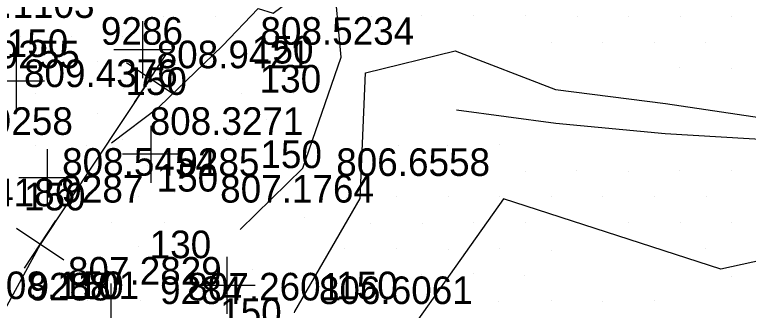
# Model space of a CAD drawing. Extents: x 1602514 to 1609837, y 863887 to 871157.
# Drawn here: x 1605194.3 to 1605395.4, y 866734.2 to 866815.2 of the extents above; entities that cross this region are included whole.
import ezdxf

# ---------------------------------------------------------------- set-up
doc = ezdxf.new("R2010")
doc.units = 0
for name, color, linetype in [('Default', 7, 'Continuous'), ('Survey-Entrances', 7, 'Continuous'), ('Survey-Point', 7, 'Continuous'), ('Survey-Ridge Lines', 7, 'Continuous'), ('Survey-Spot dirt', 7, 'Continuous'), ('Survey-Text-Elevation', 7, 'Continuous'), ('Survey-Text-Feature', 7, 'Continuous'), ('Survey-Text-Name and Number', 7, 'Continuous'), ('Survey-Vegetation trees', 7, 'Continuous')]:
    doc.layers.add(name, color=color, linetype=linetype)

msp = doc.modelspace()

# ---------------------------------------------------------------- linework, layer by layer
at = {"layer": 'Default'}
msp.add_lwpolyline([(1605231.48, 866797.64), (1605201.32, 866752.26), (1605178.92, 866711.24), (1605159.12, 866669.05), (1605154.12, 866645.56), (1605149.73, 866618.16), (1605145.78, 866600.99), (1605148.09, 866583.95), (1605152.17, 866572.39), (1605154.66, 866567.14)], dxfattribs=at)
msp.add_lwpolyline([(1605231.48, 866797.64), (1605201.32, 866752.26), (1605178.92, 866711.24), (1605159.12, 866669.05), (1605154.12, 866645.56), (1605149.73, 866618.16), (1605145.78, 866600.99), (1605148.09, 866583.95), (1605152.17, 866572.39), (1605154.66, 866567.14)], dxfattribs=at)
at = {"layer": 'Survey-Entrances'}
msp.add_lwpolyline([(1605220.9, 866780.04), (1605233.94, 866789.98), (1605251.28, 866806.63), (1605261.09, 866816.87), (1605265.22, 866815.59), (1605277.16, 866824.55), (1605284.83, 866835.5), (1605285.97, 866842.76), (1605266.64, 866853.28), (1605249.72, 866867.37), (1605246.59, 866870.64), (1605249.72, 866873.06), (1605223.7, 866894.39), (1605223.7, 866899.94), (1605224.56, 866909.9), (1605231.81, 866921.14), (1605236.92, 866929.25), (1605246.17, 866924.55), (1605248.44, 866924.98), (1605244.46, 866933.37), (1605248.44, 866951.15)], dxfattribs=at)
msp.add_lwpolyline([(1605220.9, 866780.04), (1605233.94, 866789.98), (1605251.28, 866806.63), (1605261.09, 866816.87), (1605265.22, 866815.59), (1605277.16, 866824.55), (1605284.83, 866835.5), (1605285.97, 866842.76), (1605266.64, 866853.28), (1605249.72, 866867.37), (1605246.59, 866870.64), (1605249.72, 866873.06), (1605223.7, 866894.39), (1605223.7, 866899.94), (1605224.56, 866909.9), (1605231.81, 866921.14), (1605236.92, 866929.25), (1605246.17, 866924.55), (1605248.44, 866924.98), (1605244.46, 866933.37), (1605248.44, 866951.15)], dxfattribs=at)
at = {"layer": 'Survey-Point'}
for p, q in [((1605227.15, 866791.13), (1605235.8, 866804.15)), ((1605237.98, 866793.32), (1605224.97, 866801.96)), ((1605197, 866745.75), (1605205.64, 866758.77)), ((1605207.83, 866747.93), (1605194.81, 866756.58))]:
    msp.add_line(p, q, dxfattribs=at)
at = {"layer": 'Survey-Ridge Lines'}
for points in [[(1605256.12, 866756.37), (1605273.32, 866773.13), (1605283.85, 866803.56), (1605281.75, 866826.44)], [(1605256.13, 866756.37), (1605273.32, 866773.13), (1605283.85, 866803.56), (1605281.75, 866826.44)], [(1605271.01, 866733.55), (1605271.13, 866733.84), (1605289.06, 866764.85), (1605290.46, 866799.29), (1605315.08, 866805.27), (1605342.58, 866794.72), (1605372.7, 866790.88), (1605403.41, 866786.28), (1605432.05, 866784.47), (1605463.64, 866786.21), (1605496.91, 866792.44), (1605533.57, 866796.29), (1605572.16, 866793.97)], [(1605271.13, 866733.84), (1605289.06, 866764.85), (1605290.46, 866799.29), (1605315.08, 866805.27), (1605342.58, 866794.72), (1605372.7, 866790.88), (1605403.41, 866786.28), (1605432.05, 866784.47), (1605463.64, 866786.21), (1605496.91, 866792.44), (1605533.57, 866796.29), (1605572.16, 866793.97)], [(1605315.46, 866789.1), (1605342.69, 866785.48), (1605372.69, 866782.64), (1605403.34, 866780.84), (1605431.74, 866777.29), (1605465.29, 866777.04), (1605496.99, 866781.93), (1605532.71, 866782.11), (1605571.74, 866783.81)], [(1605315.46, 866789.1), (1605342.69, 866785.48), (1605372.69, 866782.64), (1605403.34, 866780.84), (1605431.74, 866777.29), (1605465.29, 866777.04), (1605496.99, 866781.93), (1605532.71, 866782.11), (1605571.74, 866783.81)]]:
    msp.add_lwpolyline(points, dxfattribs=at)
at = {"layer": 'Survey-Spot dirt'}
for p, q in [((1605229.36, 866813.39), (1605229.36, 866797.77)), ((1605235.21, 866814.77), (1605235.21, 866814.77)), ((1605235.21, 866814.77), (1605235.21, 866814.77)), ((1605249.42, 866814.81), (1605249.42, 866814.81)), ((1605249.42, 866814.81), (1605249.42, 866814.81)), ((1605277.86, 866814.78), (1605277.86, 866814.78)), ((1605277.86, 866814.78), (1605277.86, 866814.78)), ((1605292.21, 866814.71), (1605292.21, 866814.71)), ((1605292.21, 866814.71), (1605292.21, 866814.71)), ((1605305.71, 866814.99), (1605305.71, 866814.99)), ((1605305.71, 866814.99), (1605305.71, 866814.99)), ((1605320.14, 866814.86), (1605320.14, 866814.86)), ((1605320.14, 866814.86), (1605320.14, 866814.86)), ((1605334.29, 866814.84), (1605334.29, 866814.84)), ((1605334.29, 866814.84), (1605334.29, 866814.84)), ((1605348.6, 866814.69), (1605348.6, 866814.69)), ((1605348.6, 866814.69), (1605348.6, 866814.69)), ((1605362.56, 866814.74), (1605362.56, 866814.74)), ((1605362.56, 866814.74), (1605362.56, 866814.74)), ((1605376.78, 866814.73), (1605376.78, 866814.73)), ((1605376.78, 866814.73), (1605376.78, 866814.73)), ((1605390.84, 866814.81), (1605390.84, 866814.81)), ((1605390.84, 866814.81), (1605390.84, 866814.81)), ((1605195.79, 866809.34), (1605195.79, 866809.34)), ((1605195.79, 866809.34), (1605195.79, 866809.34)), ((1605209.88, 866809.32), (1605209.88, 866809.32)), ((1605209.88, 866809.32), (1605209.88, 866809.32)), ((1605223.91, 866809.29), (1605223.91, 866809.29)), ((1605223.91, 866809.29), (1605223.91, 866809.29)), ((1605242.33, 866807.76), (1605242.33, 866807.76)), ((1605242.33, 866807.76), (1605242.33, 866807.76)), ((1605256.51, 866807.63), (1605256.51, 866807.63)), ((1605256.51, 866807.63), (1605256.51, 866807.63)), ((1605270.59, 866807.72), (1605270.59, 866807.72)), ((1605270.59, 866807.72), (1605270.59, 866807.72)), ((1605284.99, 866807.38), (1605284.99, 866807.38)), ((1605284.99, 866807.38), (1605284.99, 866807.38)), ((1605341.53, 866807.53), (1605341.53, 866807.53)), ((1605341.53, 866807.53), (1605341.53, 866807.53)), ((1605355.54, 866807.62), (1605355.54, 866807.62)), ((1605355.54, 866807.62), (1605355.54, 866807.62)), ((1605369.65, 866807.47), (1605369.65, 866807.47)), ((1605369.65, 866807.47), (1605369.65, 866807.47)), ((1605383.82, 866807.56), (1605383.82, 866807.56)), ((1605383.82, 866807.56), (1605383.82, 866807.56)), ((1605237.17, 866805.58), (1605221.54, 866805.58)), ((1605194.68, 866804.79), (1605194.68, 866789.16)), ((1605202.91, 866802.22), (1605202.91, 866802.22)), ((1605202.91, 866802.22), (1605202.91, 866802.22)), ((1605216.96, 866802.24), (1605216.96, 866802.24)), ((1605216.96, 866802.24), (1605216.96, 866802.24)), ((1605231.03, 866802.3), (1605231.03, 866802.3)), ((1605231.03, 866802.3), (1605231.03, 866802.3)), ((1605249.36, 866800.65), (1605249.36, 866800.65)), ((1605249.36, 866800.65), (1605249.36, 866800.65)), ((1605263.73, 866800.88), (1605263.73, 866800.88)), ((1605263.73, 866800.88), (1605263.73, 866800.88)), ((1605277.67, 866800.78), (1605277.67, 866800.78)), ((1605277.67, 866800.78), (1605277.67, 866800.78)), ((1605376.64, 866800.66), (1605376.64, 866800.66)), ((1605376.64, 866800.66), (1605376.64, 866800.66)), ((1605390.94, 866800.57), (1605390.94, 866800.57)), ((1605390.94, 866800.57), (1605390.94, 866800.57)), ((1605202.49, 866796.98), (1605186.87, 866796.98)), ((1605200.02, 866793.56), (1605200.02, 866793.56)), ((1605200.02, 866793.56), (1605200.02, 866793.56)), ((1605209.85, 866795.02), (1605209.85, 866795.02)), ((1605209.85, 866795.02), (1605209.85, 866795.02)), ((1605224.21, 866795.08), (1605224.21, 866795.08)), ((1605224.21, 866795.08), (1605224.21, 866795.08)), ((1605256.6, 866793.61), (1605256.6, 866793.61)), ((1605256.6, 866793.61), (1605256.6, 866793.61)), ((1605270.76, 866793.59), (1605270.76, 866793.59)), ((1605270.76, 866793.59), (1605270.76, 866793.59)), ((1605217.08, 866788.14), (1605217.08, 866788.14)), ((1605217.08, 866788.14), (1605217.08, 866788.14)), ((1605245.27, 866788.07), (1605245.27, 866788.07)), ((1605245.27, 866788.07), (1605245.27, 866788.07)), ((1605207.02, 866786.5), (1605207.02, 866786.5)), ((1605207.02, 866786.5), (1605207.02, 866786.5)), ((1605263.27, 866786.39), (1605263.27, 866786.39)), ((1605263.27, 866786.39), (1605263.27, 866786.39)), ((1605231.68, 866784.75), (1605231.68, 866769.13)), ((1605199.93, 866779.41), (1605199.93, 866779.41)), ((1605199.93, 866779.41), (1605199.93, 866779.41)), ((1605214.03, 866779.42), (1605214.03, 866779.42)), ((1605214.03, 866779.42), (1605214.03, 866779.42)), ((1605224, 866781.05), (1605224, 866781.05)), ((1605224, 866781.05), (1605224, 866781.05)), ((1605238.21, 866781.02), (1605238.21, 866781.02)), ((1605238.21, 866781.02), (1605238.21, 866781.02)), ((1605252.3, 866781.08), (1605252.3, 866781.08)), ((1605252.3, 866781.08), (1605252.3, 866781.08)), ((1605299.45, 866779.28), (1605299.45, 866779.28)), ((1605299.45, 866779.28), (1605299.45, 866779.28)), ((1605313.07, 866779.4), (1605313.07, 866779.4)), ((1605313.07, 866779.4), (1605313.07, 866779.4)), ((1605327.22, 866779.52), (1605327.22, 866779.52)), ((1605327.22, 866779.52), (1605327.22, 866779.52)), ((1605203.24, 866778.32), (1605203.24, 866762.7)), ((1605239.49, 866776.94), (1605223.86, 866776.94)), ((1605230.84, 866773.98), (1605230.84, 866773.98)), ((1605230.84, 866773.98), (1605230.84, 866773.98)), ((1605245.22, 866773.7), (1605245.22, 866773.7)), ((1605245.22, 866773.7), (1605245.22, 866773.7)), ((1605206.97, 866772.41), (1605206.97, 866772.41)), ((1605206.97, 866772.41), (1605206.97, 866772.41)), ((1605221.41, 866772.37), (1605221.41, 866772.37)), ((1605221.41, 866772.37), (1605221.41, 866772.37)), ((1605306.05, 866772.31), (1605306.05, 866772.31)), ((1605306.05, 866772.31), (1605306.05, 866772.31)), ((1605320.24, 866772.27), (1605320.24, 866772.27)), ((1605320.24, 866772.27), (1605320.24, 866772.27)), ((1605334.25, 866772.36), (1605334.25, 866772.36)), ((1605334.25, 866772.36), (1605334.25, 866772.36)), ((1605348.37, 866772.39), (1605348.37, 866772.39)), ((1605348.37, 866772.39), (1605348.37, 866772.39)), ((1605362.68, 866772.27), (1605362.68, 866772.27)), ((1605362.68, 866772.27), (1605362.68, 866772.27)), ((1605376.7, 866772.39), (1605376.7, 866772.39)), ((1605376.7, 866772.39), (1605376.7, 866772.39)), ((1605390.79, 866772.41), (1605390.79, 866772.41)), ((1605390.79, 866772.41), (1605390.79, 866772.41)), ((1605211.05, 866770.51), (1605195.43, 866770.51)), ((1605199.94, 866765.36), (1605199.94, 866765.36)), ((1605199.94, 866765.36), (1605199.94, 866765.36)), ((1605214.08, 866765.3), (1605214.08, 866765.3)), ((1605214.08, 866765.3), (1605214.08, 866765.3)), ((1605228.19, 866765.42), (1605228.19, 866765.42)), ((1605228.19, 866765.42), (1605228.19, 866765.42)), ((1605238.14, 866766.51), (1605238.14, 866766.51)), ((1605238.14, 866766.51), (1605238.14, 866766.51)), ((1605252.66, 866766.97), (1605252.66, 866766.97)), ((1605252.66, 866766.97), (1605252.66, 866766.97)), ((1605285.15, 866765.1), (1605285.15, 866765.1)), ((1605285.15, 866765.1), (1605285.15, 866765.1)), ((1605298.96, 866765.28), (1605298.96, 866765.28)), ((1605298.96, 866765.28), (1605298.96, 866765.28)), ((1605313.13, 866765.28), (1605313.13, 866765.28)), ((1605313.13, 866765.28), (1605313.13, 866765.28)), ((1605327.3, 866765.34), (1605327.3, 866765.34)), ((1605327.3, 866765.34), (1605327.3, 866765.34)), ((1605341.37, 866765.26), (1605341.37, 866765.26)), ((1605341.37, 866765.26), (1605341.37, 866765.26)), ((1605355.56, 866765.32), (1605355.56, 866765.32)), ((1605355.56, 866765.32), (1605355.56, 866765.32)), ((1605369.66, 866765.3), (1605369.66, 866765.3)), ((1605369.66, 866765.3), (1605369.66, 866765.3)), ((1605383.87, 866765.25), (1605383.87, 866765.25)), ((1605383.87, 866765.25), (1605383.87, 866765.25)), ((1605273.82, 866759.52), (1605273.82, 866759.52)), ((1605273.82, 866759.52), (1605273.82, 866759.52)), ((1605220.82, 866758.15), (1605220.82, 866758.15)), ((1605220.82, 866758.15), (1605220.82, 866758.15)), ((1605235.45, 866758.3), (1605235.45, 866758.3)), ((1605235.45, 866758.3), (1605235.45, 866758.3)), ((1605291.82, 866757.94), (1605291.82, 866757.94)), ((1605291.82, 866757.94), (1605291.82, 866757.94)), ((1605306.11, 866757.99), (1605306.11, 866757.99)), ((1605306.11, 866757.99), (1605306.11, 866757.99)), ((1605320.06, 866758.22), (1605320.06, 866758.22)), ((1605320.06, 866758.22), (1605320.06, 866758.22)), ((1605334.32, 866758.21), (1605334.32, 866758.21)), ((1605334.32, 866758.21), (1605334.32, 866758.21)), ((1605348.27, 866758.3), (1605348.27, 866758.3)), ((1605348.27, 866758.3), (1605348.27, 866758.3)), ((1605362.54, 866758.14), (1605362.54, 866758.14)), ((1605362.54, 866758.14), (1605362.54, 866758.14)), ((1605376.8, 866758.14), (1605376.8, 866758.14)), ((1605376.8, 866758.14), (1605376.8, 866758.14)), ((1605390.87, 866758.26), (1605390.87, 866758.26)), ((1605390.87, 866758.26), (1605390.87, 866758.26)), ((1605199.84, 866751.02), (1605199.84, 866751.02)), ((1605199.84, 866751.02), (1605199.84, 866751.02)), ((1605228.22, 866751.74), (1605228.22, 866751.74)), ((1605228.22, 866751.74), (1605228.22, 866751.74)), ((1605284.6, 866751.04), (1605284.6, 866751.04)), ((1605284.6, 866751.04), (1605284.6, 866751.04)), ((1605298.92, 866751.11), (1605298.92, 866751.11)), ((1605298.92, 866751.11), (1605298.92, 866751.11)), ((1605327.26, 866751.16), (1605327.26, 866751.16)), ((1605327.26, 866751.16), (1605327.26, 866751.16)), ((1605383.79, 866751.07), (1605383.79, 866751.07)), ((1605383.79, 866751.07), (1605383.79, 866751.07)), ((1605242.21, 866750.89), (1605242.21, 866750.89)), ((1605242.21, 866750.89), (1605242.21, 866750.89)), ((1605313.19, 866750.75), (1605313.19, 866750.75)), ((1605313.19, 866750.75), (1605313.19, 866750.75)), ((1605341.49, 866750.7), (1605341.49, 866750.7)), ((1605341.49, 866750.7), (1605341.49, 866750.7)), ((1605252.47, 866748.82), (1605252.47, 866733.2)), ((1605259.59, 866745.32), (1605259.59, 866745.32)), ((1605259.59, 866745.32), (1605259.59, 866745.32)), ((1605206.86, 866744.21), (1605206.86, 866744.21)), ((1605206.86, 866744.21), (1605206.86, 866744.21)), ((1605220.9, 866743.66), (1605220.9, 866743.66)), ((1605220.9, 866743.66), (1605220.9, 866743.66)), ((1605235.03, 866744.18), (1605235.03, 866744.18)), ((1605235.03, 866744.18), (1605235.03, 866744.18)), ((1605291.87, 866744.02), (1605291.87, 866744.02)), ((1605291.87, 866744.02), (1605291.87, 866744.02)), ((1605305.77, 866743.9), (1605305.77, 866743.9)), ((1605305.77, 866743.9), (1605305.77, 866743.9)), ((1605320.1, 866744.25), (1605320.1, 866744.25)), ((1605320.1, 866744.25), (1605320.1, 866744.25)), ((1605334.15, 866743.69), (1605334.15, 866743.69)), ((1605334.15, 866743.69), (1605334.15, 866743.69)), ((1605390.97, 866743.57), (1605390.97, 866743.57)), ((1605390.97, 866743.57), (1605390.97, 866743.57)), ((1605220.65, 866741.53), (1605220.65, 866725.9)), ((1605260.29, 866741.01), (1605244.66, 866741.01)), ((1605252.51, 866738.34), (1605252.51, 866738.34)), ((1605252.51, 866738.34), (1605252.51, 866738.34)), ((1605266.95, 866738.51), (1605266.95, 866738.51)), ((1605266.95, 866738.51), (1605266.95, 866738.51)), ((1605298.91, 866736.96), (1605298.91, 866736.96)), ((1605298.91, 866736.96), (1605298.91, 866736.96)), ((1605312.94, 866737), (1605312.94, 866737)), ((1605312.94, 866737), (1605312.94, 866737)), ((1605214.4, 866736.89), (1605214.4, 866736.89)), ((1605214.4, 866736.89), (1605214.4, 866736.89)), ((1605228.71, 866736.85), (1605228.71, 866736.85)), ((1605228.71, 866736.85), (1605228.71, 866736.85)), ((1605284.8, 866736.79), (1605284.8, 866736.79)), ((1605284.8, 866736.79), (1605284.8, 866736.79)), ((1605326.98, 866736.65), (1605326.98, 866736.65)), ((1605326.98, 866736.65), (1605326.98, 866736.65)), ((1605341.49, 866736.78), (1605341.49, 866736.78)), ((1605341.49, 866736.78), (1605341.49, 866736.78)), ((1605355.58, 866736.64), (1605355.58, 866736.64)), ((1605355.58, 866736.64), (1605355.58, 866736.64)), ((1605369.77, 866736.86), (1605369.77, 866736.86)), ((1605369.77, 866736.86), (1605369.77, 866736.86))]:
    msp.add_line(p, q, dxfattribs=at)
at = {"layer": 'Survey-Vegetation trees'}
msp.add_lwpolyline([(1605601.79, 866275.83), (1605605.2, 866448.65), (1605612.42, 866530.39), (1605609.93, 866556.1), (1605459.73, 866746.47), (1605424.26, 866753.41), (1605387.87, 866745.45), (1605328.37, 866764.72), (1605298.66, 866722.79), (1605306.28, 866699.16), (1605277.32, 866658.75), (1605265.13, 866625.97), (1605217.79, 866602.88), (1605158.36, 866628.8), (1605148.45, 866592.97), (1605247.5, 866507.58), (1605323.27, 866431.24), (1605384.81, 866367.9), (1605438.61, 866328.19), (1605473.87, 866349.1), (1605499.88, 866323.66)], dxfattribs=at)
msp.add_lwpolyline([(1605601.79, 866275.83), (1605605.2, 866448.65), (1605612.42, 866530.39), (1605609.93, 866556.1), (1605459.73, 866746.47), (1605424.26, 866753.41), (1605387.87, 866745.45), (1605328.37, 866764.72), (1605298.66, 866722.79), (1605306.28, 866699.16), (1605277.32, 866658.75), (1605265.13, 866625.97), (1605217.79, 866602.88), (1605158.36, 866628.8), (1605148.45, 866592.97), (1605247.5, 866507.58), (1605323.27, 866431.24), (1605384.81, 866367.9), (1605438.61, 866328.19), (1605473.87, 866349.1), (1605499.88, 866323.66)], dxfattribs=at)

# ---------------------------------------------------------------- texts
at = {"layer": 'Survey-Text-Elevation'}
for s, p in [('811.1103', (1605174.04, 866814.3)), ('811.1103', (1605174.04, 866814.3)), ('808.5234', (1605261.68, 866806.94)), ('808.5234', (1605261.68, 866806.94)), ('808.9421', (1605233.24, 866800.51)), ('808.9421', (1605233.24, 866800.51)), ('809.4376', (1605196.86, 866795.35)), ('809.4376', (1605196.86, 866795.35)), ('808.3271', (1605231.32, 866782.26)), ('808.3271', (1605231.32, 866782.26)), ('808.5454', (1605207.32, 866771.06)), ('808.5454', (1605207.32, 866771.06)), ('806.6558', (1605282.47, 866771.01)), ('806.6558', (1605282.47, 866771.01)), ('807.1764', (1605250.65, 866763.71)), ('807.1764', (1605250.65, 866763.71)), ('809.4186', (1605168.73, 866762.72)), ('809.4186', (1605168.73, 866762.72)), ('807.2829', (1605208.92, 866741.24)), ('807.2829', (1605208.92, 866741.24)), ('808.1101', (1605186.27, 866737.27)), ('808.1101', (1605186.27, 866737.27)), ('807.2601', (1605241.65, 866736.9)), ('807.2601', (1605241.65, 866736.9)), ('806.6061', (1605277.73, 866735.92)), ('806.6061', (1605277.73, 866735.92))]:
    msp.add_text(s, height=7.56, dxfattribs=at).set_placement(p)
at = {"layer": 'Survey-Text-Feature'}
for s, p in [('150', (1605192.15, 866803.58)), ('150', (1605192.15, 866803.58)), ('150', (1605259.36, 866801.8)), ('150', (1605259.36, 866801.8)), ('130', (1605261.48, 866793.86)), ('130', (1605261.48, 866793.86)), ('150', (1605224.68, 866793.2)), ('150', (1605224.68, 866793.2)), ('150', (1605261.68, 866773.16)), ('150', (1605261.68, 866773.16)), ('150', (1605233.24, 866766.73)), ('150', (1605233.24, 866766.73)), ('150', (1605196.86, 866761.57)), ('150', (1605196.86, 866761.57)), ('130', (1605231.32, 866748.48)), ('130', (1605231.32, 866748.48)), ('150', (1605207.32, 866737.28)), ('150', (1605207.32, 866737.28)), ('150', (1605282.47, 866737.23)), ('150', (1605282.47, 866737.23)), ('150', (1605250.65, 866729.93)), ('150', (1605250.65, 866729.93))]:
    msp.add_text(s, height=7.56, dxfattribs=at).set_placement(p)
at = {"layer": 'Survey-Text-Name and Number'}
for s, p in [('9286', (1605217.95, 866806.94)), ('9286', (1605217.95, 866806.94)), ('9255', (1605189.68, 866800.51)), ('9255', (1605189.68, 866800.51)), ('9258', (1605187.78, 866782.26)), ('9258', (1605187.78, 866782.26)), ('9285', (1605238.92, 866771.01)), ('9285', (1605238.92, 866771.01)), ('9287', (1605207.11, 866763.71)), ('9287', (1605207.11, 866763.71)), ('9288', (1605198.11, 866736.9)), ('9288', (1605198.11, 866736.9)), ('9284', (1605234.18, 866735.92)), ('9284', (1605234.18, 866735.92))]:
    msp.add_text(s, height=7.56, dxfattribs=at).set_placement(p)

doc.saveas('drawing.dxf')
